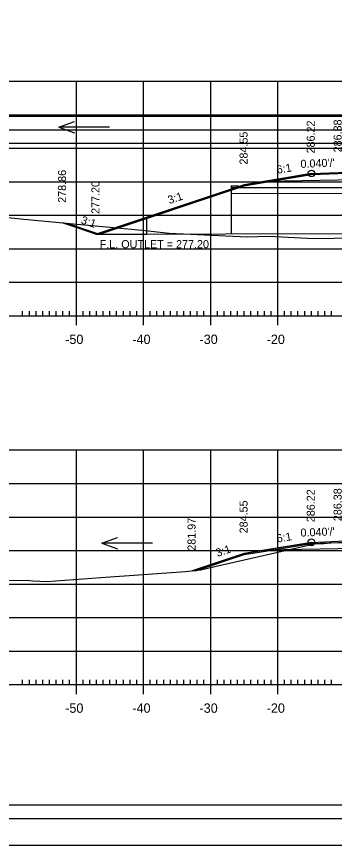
# Model space of a CAD drawing. Extents: x 1368713 to 1370673, y 380279 to 380950.
# Drawn here: x 1370450.7 to 1370498.1, y 380523.8 to 380647.4 of the extents above; entities that cross this region are included whole.
import ezdxf

# ---------------------------------------------------------------- set-up
doc = ezdxf.new("R2010")
doc.units = 0
for name, color, linetype in [('R_Alt Surface', 7, 'Continuous'), ('R_Axis', 7, 'Continuous'), ('R_Axis Annot', 7, 'Continuous'), ('R_Border', 7, 'Continuous'), ('R_Border Plan-Plan', 7, 'Continuous'), ('R_Exist Surface', 7, 'Continuous'), ('R_Fin Surface', 7, 'Continuous'), ('R_Grid', 7, 'Continuous'), ('R_No Plot', 7, 'Continuous'), ('R_Water', 7, 'Continuous'), ('R_Water Annot', 7, 'Continuous'), ('R_Xsect Elev', 7, 'Continuous'), ('R_Xsect Slope', 7, 'Continuous')]:
    doc.layers.add(name, color=color, linetype=linetype)

msp = doc.modelspace()

# ---------------------------------------------------------------- linework, layer by layer
at = {"layer": 'R_Alt Surface'}
for points in [[(1370458.29, 380616.55), (1370460.53, 380615.8), (1370463.07, 380614.95), (1370484.63, 380622.14), (1370487.79, 380622.67), (1370494.63, 380623.81), (1370498.63, 380623.97), (1370509.63, 380624.19), (1370520.63, 380624.18), (1370534.63, 380624.17), (1370536.01, 380622.79), (1370536.87, 380621.93)], [(1370494.63, 380623.97), (1370484.63, 380622.31)], [(1370487.79, 380622.83), (1370498.63, 380623.05), (1370509.63, 380623.27), (1370520.63, 380623.26), (1370532.55, 380623.03)], [(1370484.63, 380622.31), (1370462.57, 380614.95)], [(1370462.57, 380614.95), (1370462.57, 380614.95), (1370457.6, 380616.61)], [(1370477.26, 380564.76), (1370477.38, 380564.72), (1370484.63, 380567.14), (1370487.79, 380567.67), (1370494.63, 380568.81), (1370498.63, 380568.97), (1370509.63, 380569.19), (1370520.63, 380569.29), (1370534.63, 380569.42), (1370537.74, 380567.86), (1370544.18, 380564.64)], [(1370494.63, 380568.97), (1370484.63, 380567.31)], [(1370484.63, 380567.31), (1370476.88, 380564.72)], [(1370487.79, 380567.83), (1370498.63, 380568.05), (1370509.63, 380568.27), (1370520.63, 380568.37), (1370532.81, 380568.13)], [(1370476.88, 380564.72), (1370476.88, 380564.72), (1370476.88, 380564.72)]]:
    msp.add_lwpolyline(points, dxfattribs=at)
at = {"layer": 'R_Axis'}
for p, q in [((1370451.63, 380602.75), (1370451.63, 380603.45)), ((1370452.63, 380602.75), (1370452.63, 380603.45)), ((1370453.63, 380602.75), (1370453.63, 380603.45)), ((1370454.63, 380602.75), (1370454.63, 380603.45)), ((1370455.63, 380602.75), (1370455.63, 380603.45)), ((1370456.63, 380602.75), (1370456.63, 380603.45)), ((1370457.63, 380602.75), (1370457.63, 380603.45)), ((1370458.63, 380602.75), (1370458.63, 380603.45)), ((1370459.63, 380601.35), (1370459.63, 380604.15)), ((1370460.63, 380602.75), (1370460.63, 380603.45)), ((1370461.63, 380602.75), (1370461.63, 380603.45)), ((1370462.63, 380602.75), (1370462.63, 380603.45)), ((1370463.63, 380602.75), (1370463.63, 380603.45)), ((1370464.63, 380602.75), (1370464.63, 380603.45)), ((1370465.63, 380602.75), (1370465.63, 380603.45)), ((1370466.63, 380602.75), (1370466.63, 380603.45)), ((1370467.63, 380602.75), (1370467.63, 380603.45)), ((1370468.63, 380602.75), (1370468.63, 380603.45)), ((1370469.63, 380601.35), (1370469.63, 380604.15)), ((1370470.63, 380602.75), (1370470.63, 380603.45)), ((1370471.63, 380602.75), (1370471.63, 380603.45)), ((1370472.63, 380602.75), (1370472.63, 380603.45)), ((1370473.63, 380602.75), (1370473.63, 380603.45)), ((1370474.63, 380602.75), (1370474.63, 380603.45)), ((1370475.63, 380602.75), (1370475.63, 380603.45)), ((1370476.63, 380602.75), (1370476.63, 380603.45)), ((1370477.63, 380602.75), (1370477.63, 380603.45)), ((1370478.63, 380602.75), (1370478.63, 380603.45)), ((1370479.63, 380601.35), (1370479.63, 380604.15)), ((1370480.63, 380602.75), (1370480.63, 380603.45)), ((1370481.63, 380602.75), (1370481.63, 380603.45)), ((1370482.63, 380602.75), (1370482.63, 380603.45)), ((1370483.63, 380602.75), (1370483.63, 380603.45)), ((1370484.63, 380602.75), (1370484.63, 380603.45)), ((1370485.63, 380602.75), (1370485.63, 380603.45)), ((1370486.63, 380602.75), (1370486.63, 380603.45)), ((1370487.63, 380602.75), (1370487.63, 380603.45)), ((1370488.63, 380602.75), (1370488.63, 380603.45)), ((1370489.63, 380601.35), (1370489.63, 380604.15)), ((1370490.63, 380602.75), (1370490.63, 380603.45)), ((1370491.63, 380602.75), (1370491.63, 380603.45)), ((1370492.63, 380602.75), (1370492.63, 380603.45)), ((1370493.63, 380602.75), (1370493.63, 380603.45)), ((1370494.63, 380602.75), (1370494.63, 380603.45)), ((1370495.63, 380602.75), (1370495.63, 380603.45)), ((1370496.63, 380602.75), (1370496.63, 380603.45)), ((1370497.63, 380602.75), (1370497.63, 380603.45)), ((1370369.63, 380602.75), (1370649.63, 380602.75)), ((1370459.63, 380546.35), (1370459.63, 380549.15)), ((1370469.63, 380546.35), (1370469.63, 380549.15)), ((1370479.63, 380546.35), (1370479.63, 380549.15)), ((1370489.63, 380546.35), (1370489.63, 380549.15)), ((1370369.63, 380547.75), (1370649.63, 380547.75)), ((1370451.63, 380547.75), (1370451.63, 380548.45)), ((1370452.63, 380547.75), (1370452.63, 380548.45)), ((1370453.63, 380547.75), (1370453.63, 380548.45)), ((1370454.63, 380547.75), (1370454.63, 380548.45)), ((1370455.63, 380547.75), (1370455.63, 380548.45)), ((1370456.63, 380547.75), (1370456.63, 380548.45)), ((1370457.63, 380547.75), (1370457.63, 380548.45)), ((1370458.63, 380547.75), (1370458.63, 380548.45)), ((1370460.63, 380547.75), (1370460.63, 380548.45)), ((1370461.63, 380547.75), (1370461.63, 380548.45)), ((1370462.63, 380547.75), (1370462.63, 380548.45)), ((1370463.63, 380547.75), (1370463.63, 380548.45)), ((1370464.63, 380547.75), (1370464.63, 380548.45)), ((1370465.63, 380547.75), (1370465.63, 380548.45)), ((1370466.63, 380547.75), (1370466.63, 380548.45)), ((1370467.63, 380547.75), (1370467.63, 380548.45)), ((1370468.63, 380547.75), (1370468.63, 380548.45)), ((1370470.63, 380547.75), (1370470.63, 380548.45)), ((1370471.63, 380547.75), (1370471.63, 380548.45)), ((1370472.63, 380547.75), (1370472.63, 380548.45)), ((1370473.63, 380547.75), (1370473.63, 380548.45)), ((1370474.63, 380547.75), (1370474.63, 380548.45)), ((1370475.63, 380547.75), (1370475.63, 380548.45)), ((1370476.63, 380547.75), (1370476.63, 380548.45)), ((1370477.63, 380547.75), (1370477.63, 380548.45)), ((1370478.63, 380547.75), (1370478.63, 380548.45)), ((1370480.63, 380547.75), (1370480.63, 380548.45)), ((1370481.63, 380547.75), (1370481.63, 380548.45)), ((1370482.63, 380547.75), (1370482.63, 380548.45)), ((1370483.63, 380547.75), (1370483.63, 380548.45)), ((1370484.63, 380547.75), (1370484.63, 380548.45)), ((1370485.63, 380547.75), (1370485.63, 380548.45)), ((1370486.63, 380547.75), (1370486.63, 380548.45)), ((1370487.63, 380547.75), (1370487.63, 380548.45)), ((1370488.63, 380547.75), (1370488.63, 380548.45)), ((1370490.63, 380547.75), (1370490.63, 380548.45)), ((1370491.63, 380547.75), (1370491.63, 380548.45)), ((1370492.63, 380547.75), (1370492.63, 380548.45)), ((1370493.63, 380547.75), (1370493.63, 380548.45)), ((1370494.63, 380547.75), (1370494.63, 380548.45)), ((1370495.63, 380547.75), (1370495.63, 380548.45)), ((1370496.63, 380547.75), (1370496.63, 380548.45)), ((1370497.63, 380547.75), (1370497.63, 380548.45))]:
    msp.add_line(p, q, dxfattribs=at)
at = {"layer": 'R_Border'}
msp.add_line((1370667.81, 380527.75), (1370351.63, 380527.75), dxfattribs=at)
at = {"layer": 'R_Border Plan-Plan'}
msp.add_line((1370351.63, 380630.48), (1370667.81, 380630.48), dxfattribs=at)
at = {"layer": 'R_Exist Surface'}
for points in [[(1370449.47, 380617.4), (1370451.79, 380617.16), (1370452.42, 380617.11), (1370457.08, 380616.66), (1370469.44, 380615.53), (1370473.45, 380615.06), (1370485.06, 380614.51), (1370488.22, 380614.64), (1370495.03, 380614.29), (1370501.02, 380614.36), (1370508.48, 380614.62), (1370515.29, 380614.68), (1370522.01, 380614.91), (1370532.68, 380615.19), (1370535.71, 380615.26), (1370537.26, 380615.31), (1370546.95, 380616.58), (1370549.49, 380616.66), (1370557.21, 380617.33), (1370564.3, 380618.98), (1370565.21, 380619.3), (1370566.89, 380619.26), (1370581.75, 380619.73)], [(1370449.57, 380563.26), (1370452.15, 380563.35), (1370453.14, 380563.23), (1370455.22, 380563.14), (1370463.27, 380563.72), (1370475.86, 380564.62), (1370478.14, 380564.85), (1370480.24, 380565.38), (1370495.11, 380568.73), (1370496.49, 380568.81), (1370497.53, 380568.91), (1370502.28, 380569.02)]]:
    msp.add_lwpolyline(points, dxfattribs=at)
at = {"layer": 'R_Fin Surface'}
for points in [[(1370457.6, 380616.61), (1370459.86, 380615.86), (1370462.57, 380614.95), (1370484.63, 380622.31), (1370487.79, 380622.83), (1370494.63, 380623.97), (1370498.63, 380624.13), (1370509.63, 380624.35), (1370520.63, 380624.35), (1370524.63, 380624.35), (1370532.55, 380623.03), (1370534.63, 380622.68), (1370557.21, 380615.15), (1370559.22, 380615.82), (1370569.81, 380619.36)], [(1370494.63, 380623.97), (1370498.63, 380624.13), (1370509.63, 380624.35), (1370520.63, 380624.35), (1370524.63, 380624.35)], [(1370476.88, 380564.72), (1370476.88, 380564.72), (1370484.63, 380567.31), (1370487.79, 380567.83), (1370494.63, 380568.97), (1370498.63, 380569.13), (1370509.63, 380569.35), (1370520.63, 380569.45), (1370524.63, 380569.49), (1370532.81, 380568.13), (1370534.63, 380567.82), (1370553.89, 380561.41), (1370563.83, 380564.72)], [(1370494.63, 380568.97), (1370498.63, 380569.13), (1370509.63, 380569.35), (1370520.63, 380569.45), (1370524.63, 380569.49)]]:
    msp.add_lwpolyline(points, dxfattribs=at)
at = {"layer": 'R_Grid'}
for p, q in [((1370369.63, 380637.75), (1370649.63, 380637.75)), ((1370459.63, 380602.75), (1370459.63, 380637.75)), ((1370469.63, 380602.75), (1370469.63, 380637.75)), ((1370479.63, 380602.75), (1370479.63, 380637.75)), ((1370489.63, 380602.75), (1370489.63, 380637.75)), ((1370369.63, 380632.75), (1370649.63, 380632.75)), ((1370369.63, 380627.75), (1370649.63, 380627.75)), ((1370369.63, 380622.75), (1370649.63, 380622.75)), ((1370369.63, 380617.75), (1370649.63, 380617.75)), ((1370369.63, 380612.75), (1370649.63, 380612.75)), ((1370369.63, 380607.75), (1370649.63, 380607.75)), ((1370369.63, 380602.75), (1370649.63, 380602.75)), ((1370369.63, 380582.75), (1370649.63, 380582.75)), ((1370459.63, 380547.75), (1370459.63, 380582.75)), ((1370469.63, 380547.75), (1370469.63, 380582.75)), ((1370479.63, 380547.75), (1370479.63, 380582.75)), ((1370489.63, 380547.75), (1370489.63, 380582.75)), ((1370369.63, 380577.75), (1370649.63, 380577.75)), ((1370369.63, 380572.75), (1370649.63, 380572.75)), ((1370369.63, 380567.75), (1370649.63, 380567.75)), ((1370369.63, 380562.75), (1370649.63, 380562.75)), ((1370369.63, 380557.75), (1370649.63, 380557.75)), ((1370369.63, 380552.75), (1370649.63, 380552.75)), ((1370369.63, 380547.75), (1370649.63, 380547.75))]:
    msp.add_line(p, q, dxfattribs=at)
at = {"layer": 'R_No Plot'}
for points in [[(1370339.22, 380737.11), (1370672.56, 380737.11), (1370672.56, 380523.77), (1370339.22, 380523.77)], [(1370665.81, 380632.48), (1370353.63, 380632.48), (1370353.63, 380731.21), (1370603.17, 380731.21), (1370603.17, 380721.33), (1370620.71, 380721.33), (1370644.81, 380721.33), (1370644.81, 380699), (1370665.81, 380699)], [(1370353.63, 380731.21), (1370603.17, 380731.21), (1370603.17, 380721.33), (1370620.71, 380721.33), (1370644.81, 380721.33), (1370644.81, 380699), (1370665.81, 380699), (1370665.81, 380529.75), (1370353.63, 380529.75)], [(1370353.63, 380628.48), (1370665.81, 380628.48), (1370665.81, 380529.75), (1370353.63, 380529.75)]]:
    msp.add_lwpolyline(points, close=True, dxfattribs=at)
for centre in [(1370494.63, 380623.97), (1370494.63, 380623.97), (1370494.63, 380568.97), (1370494.63, 380568.97)]:
    msp.add_circle(centre, 0.5, dxfattribs=at)
at = {"layer": 'R_Water'}
for p, q in [((1370482.7, 380622.12), (1370482.7, 380615)), ((1370482.7, 380622.12), (1370483.7, 380622.12)), ((1370482.7, 380621.87), (1370537.34, 380621.99)), ((1370483.7, 380622.12), (1370483.7, 380621.87)), ((1370482.7, 380621), (1370537.34, 380621.11)), ((1370470.12, 380614.97), (1370470.12, 380617.47)), ((1370462.57, 380614.95), (1370557.21, 380615.15)), ((1370462.57, 380614.95), (1370470.12, 380614.95))]:
    msp.add_line(p, q, dxfattribs=at)
at = {"layer": 'R_Water Annot'}
for p, q in [((1370457.04, 380630.87), (1370459.35, 380631.71)), ((1370464.58, 380630.87), (1370457.04, 380630.87)), ((1370457.04, 380630.87), (1370459.35, 380630.03)), ((1370463.43, 380568.83), (1370465.74, 380569.67)), ((1370470.97, 380568.83), (1370463.43, 380568.83)), ((1370463.43, 380568.83), (1370465.74, 380567.99))]:
    msp.add_line(p, q, dxfattribs=at)

# ---------------------------------------------------------------- texts
at = {"layer": 'R_Axis Annot'}
for s, p in [('-50', (1370457.97, 380598.55)), ('-40', (1370467.97, 380598.55)), ('-30', (1370477.97, 380598.55)), ('-20', (1370487.97, 380598.55)), ('-50', (1370457.97, 380543.55)), ('-40', (1370467.97, 380543.55)), ('-30', (1370477.97, 380543.55)), ('-20', (1370487.97, 380543.55))]:
    msp.add_text(s, height=1.4, dxfattribs=at).set_placement(p)
at = {"layer": 'R_Xsect Elev'}
for s, p in [('286.22', (1370495.13, 380626.97)), ('286.38', (1370499.13, 380627.13)), ('284.55', (1370485.13, 380625.31)), ('278.86', (1370458.1, 380619.61)), ('277.20', (1370463.07, 380617.95)), ('286.22', (1370495.13, 380571.97)), ('286.38', (1370499.13, 380572.13)), ('284.55', (1370485.13, 380570.31)), ('281.97', (1370477.38, 380567.72)), ('281.97', (1370477.38, 380567.72))]:
    msp.add_text(s, height=1.2, rotation=90, dxfattribs=at).set_placement(p)
at = {"layer": 'R_Xsect Slope'}
for s, rotation, p in [('6:1', 9.4623, (1370489.56, 380623.93)), ("0.040'/'", 2.2906, (1370493.03, 380624.81)), ('3:1', 18.4349, (1370473.47, 380619.41)), ('3:1', 341.5651, (1370460.21, 380616.56)), ('F.L. OUTLET = 277.20', 360, (1370463.1, 380612.84)), ("0.040'/'", 2.2906, (1370493.03, 380569.81)), ('6:1', 9.4623, (1370489.56, 380568.93)), ('3:1', 18.4349, (1370480.63, 380566.79))]:
    msp.add_text(s, height=1.2, rotation=rotation, dxfattribs=at).set_placement(p)

doc.saveas('drawing.dxf')
